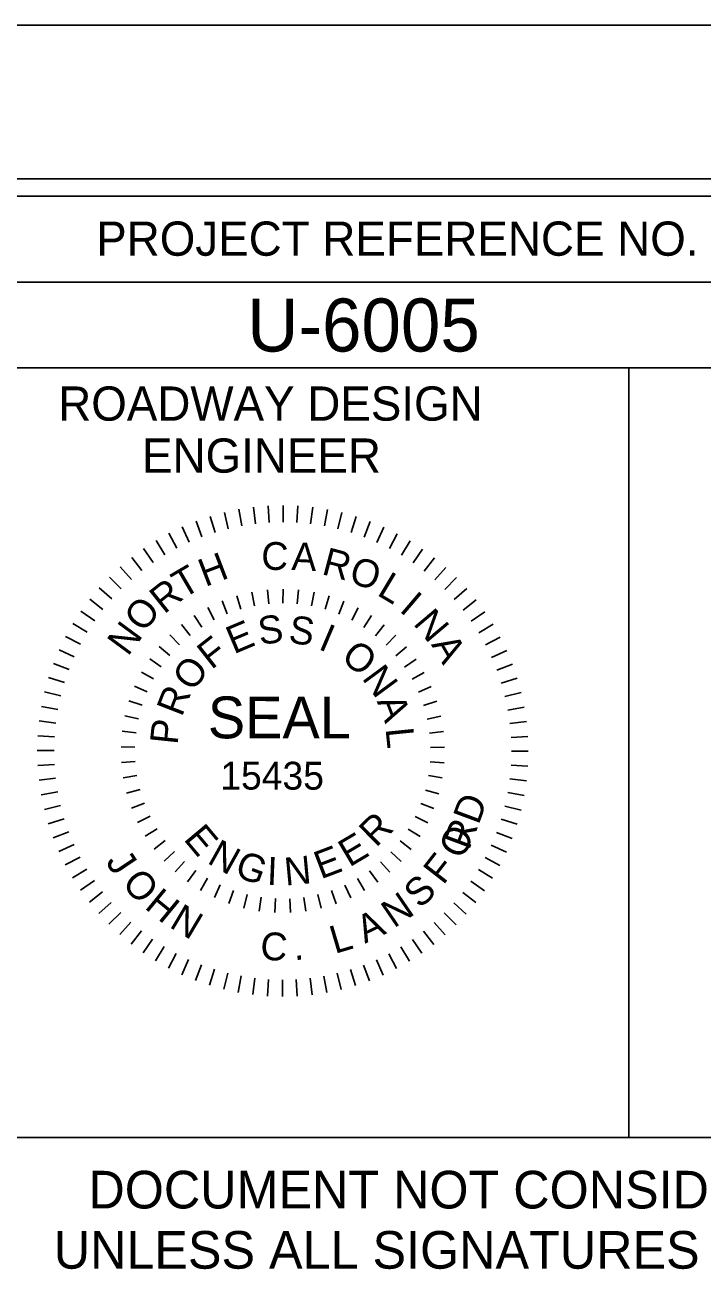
# Model space of a CAD drawing. Extents: x 1624665 to 1626605, y 896887 to 897987.
# Drawn here: x 1626144.2 to 1626243.2, y 897803.5 to 897987.4 of the extents above; entities that cross this region are included whole.
import ezdxf

# ---------------------------------------------------------------- set-up
doc = ezdxf.new("R2010")
doc.units = 0
for name, color, linetype in [('Old_Level_21', 7, 'Continuous'), ('Sheet Cutting Line CELL', 7, 'Continuous'), ('Sheet Data Field CELL', 7, 'Continuous'), ('Sheet Plot Border Inside CELL', 7, 'Continuous'), ('Sheet Plot Border Outside CELL', 7, 'Continuous'), ('Sheet Profile CELL', 7, 'Continuous'), ('Sheet Profile Grid Major CELL', 7, 'Continuous'), ('Sheet Sticker Exception Certification CELL', 7, 'Continuous')]:
    doc.layers.add(name, color=color, linetype=linetype)

msp = doc.modelspace()

# ---------------------------------------------------------------- linework, layer by layer
at = {"layer": 'Old_Level_21'}
for p, q in [((1626173.3, 897916.24), (1626173.87, 897913.87)), ((1626175.41, 897916.7), (1626175.85, 897914.29)), ((1626177.56, 897917.02), (1626177.85, 897914.59)), ((1626179.72, 897917.21), (1626179.86, 897914.77)), ((1626181.88, 897917.27), (1626181.88, 897914.83)), ((1626184.05, 897917.2), (1626183.9, 897914.76)), ((1626186.21, 897917), (1626185.91, 897914.58)), ((1626188.35, 897916.68), (1626187.91, 897914.27)), ((1626190.47, 897916.22), (1626189.88, 897913.85)), ((1626167.15, 897914.13), (1626168.15, 897911.9)), ((1626169.16, 897914.96), (1626170.02, 897912.67)), ((1626171.2, 897915.67), (1626171.93, 897913.33)), ((1626192.56, 897915.64), (1626191.83, 897913.3)), ((1626194.6, 897914.93), (1626193.73, 897912.64)), ((1626196.6, 897914.09), (1626195.6, 897911.86)), ((1626165.2, 897913.19), (1626166.34, 897911.02)), ((1626198.55, 897913.14), (1626197.41, 897910.98)), ((1626161.49, 897910.95), (1626162.88, 897908.94)), ((1626163.31, 897912.12), (1626164.58, 897910.03)), ((1626200.44, 897912.07), (1626199.17, 897909.98)), ((1626202.26, 897910.89), (1626200.87, 897908.88)), ((1626159.75, 897909.67), (1626161.25, 897907.74)), ((1626204, 897909.61), (1626202.49, 897907.68)), ((1626156.5, 897906.8), (1626158.22, 897905.07)), ((1626158.08, 897908.28), (1626159.7, 897906.45)), ((1626205.67, 897908.22), (1626204.04, 897906.39)), ((1626207.24, 897906.73), (1626205.51, 897905)), ((1626155.01, 897905.22), (1626156.84, 897903.6)), ((1626179.58, 897904.93), (1626179.78, 897902.91)), ((1626181.87, 897905.04), (1626181.86, 897903)), ((1626181.86, 897903), (1626181.87, 897905.04)), ((1626184.15, 897904.93), (1626183.95, 897902.9)), ((1626208.72, 897905.15), (1626206.89, 897903.53)), ((1626153.62, 897903.56), (1626155.54, 897902.05)), ((1626172.95, 897903.31), (1626173.71, 897901.42)), ((1626175.1, 897904.06), (1626175.68, 897902.11)), ((1626177.32, 897904.61), (1626177.71, 897902.61)), ((1626186.41, 897904.59), (1626186.02, 897902.59)), ((1626188.63, 897904.05), (1626188.04, 897902.09)), ((1626190.78, 897903.28), (1626190.01, 897901.4)), ((1626210.11, 897903.48), (1626208.18, 897901.98)), ((1626152.33, 897901.82), (1626154.34, 897900.42)), ((1626170.87, 897902.35), (1626171.81, 897900.54)), ((1626192.85, 897902.32), (1626191.91, 897900.51)), ((1626211.39, 897901.73), (1626209.38, 897900.35)), ((1626151.15, 897900), (1626153.24, 897898.73)), ((1626167.05, 897899.85), (1626168.32, 897898.26)), ((1626168.9, 897901.19), (1626170.01, 897899.48)), ((1626194.82, 897901.16), (1626193.7, 897899.45)), ((1626196.67, 897899.81), (1626195.39, 897898.22)), ((1626212.57, 897899.91), (1626210.47, 897898.65)), ((1626150.08, 897898.11), (1626152.25, 897896.97)), ((1626165.34, 897898.34), (1626166.76, 897896.88)), ((1626198.38, 897898.29), (1626196.95, 897896.83)), ((1626213.63, 897898.02), (1626211.46, 897896.89)), ((1626149.14, 897896.16), (1626151.36, 897895.16)), ((1626163.78, 897896.67), (1626165.33, 897895.35)), ((1626199.93, 897896.62), (1626198.37, 897895.31)), ((1626214.57, 897896.07), (1626212.34, 897895.07)), ((1626148.3, 897894.16), (1626150.59, 897893.29)), ((1626162.39, 897894.85), (1626164.06, 897893.69)), ((1626201.32, 897894.8), (1626199.64, 897893.64)), ((1626215.4, 897894.07), (1626213.11, 897893.2)), ((1626147.59, 897892.12), (1626149.93, 897891.39)), ((1626161.18, 897892.92), (1626162.96, 897891.92)), ((1626202.52, 897892.86), (1626200.74, 897891.87)), ((1626216.11, 897892.02), (1626213.77, 897891.3)), ((1626160.16, 897890.87), (1626162.03, 897890.05)), ((1626203.53, 897890.81), (1626201.66, 897889.99)), ((1626147, 897890.03), (1626149.38, 897889.44)), ((1626159.35, 897888.73), (1626161.29, 897888.1)), ((1626204.33, 897888.67), (1626202.39, 897888.04)), ((1626216.69, 897889.93), (1626214.31, 897889.35)), ((1626146.55, 897887.91), (1626148.95, 897887.47)), ((1626158.75, 897886.53), (1626160.74, 897886.09)), ((1626217.14, 897887.81), (1626214.73, 897887.37)), ((1626146.22, 897885.77), (1626148.65, 897885.47)), ((1626204.93, 897886.46), (1626202.94, 897886.03)), ((1626217.46, 897885.67), (1626215.03, 897885.38)), ((1626146.02, 897883.61), (1626148.46, 897883.46)), ((1626158.36, 897884.27), (1626160.38, 897884.03)), ((1626205.31, 897884.21), (1626203.29, 897883.97)), ((1626217.65, 897883.51), (1626215.21, 897883.37)), ((1626145.95, 897881.44), (1626148.4, 897881.44)), ((1626158.19, 897882), (1626160.23, 897881.94)), ((1626205.48, 897881.93), (1626203.44, 897881.88)), ((1626217.71, 897881.34), (1626215.27, 897881.35)), ((1626146.01, 897879.27), (1626148.46, 897879.42)), ((1626158.24, 897879.71), (1626160.27, 897879.86)), ((1626205.42, 897879.65), (1626203.39, 897879.8)), ((1626217.65, 897879.17), (1626215.21, 897879.32)), ((1626146.21, 897877.12), (1626148.63, 897877.41)), ((1626158.52, 897877.44), (1626160.52, 897877.78)), ((1626203.14, 897877.79), (1626205.15, 897877.45)), ((1626217.45, 897877.02), (1626215.02, 897877.31)), ((1626159, 897875.21), (1626160.97, 897875.74)), ((1626204.64, 897875.14), (1626202.68, 897875.68)), ((1626146.53, 897874.97), (1626148.93, 897875.41)), ((1626159.71, 897873.03), (1626161.62, 897873.75)), ((1626203.93, 897872.97), (1626202.03, 897873.7)), ((1626217.12, 897874.87), (1626214.71, 897875.32)), ((1626146.98, 897872.86), (1626149.36, 897873.43)), ((1626160.62, 897870.94), (1626162.45, 897871.84)), ((1626203.02, 897870.88), (1626201.19, 897871.79)), ((1626216.66, 897872.76), (1626214.29, 897873.34)), ((1626147.56, 897870.76), (1626149.9, 897871.49)), ((1626161.72, 897868.94), (1626163.46, 897870.01)), ((1626201.91, 897868.89), (1626200.17, 897869.96)), ((1626216.08, 897870.67), (1626213.74, 897871.4)), ((1626148.26, 897868.72), (1626150.55, 897869.58)), ((1626163.02, 897867.06), (1626164.64, 897868.29)), ((1626200.61, 897867), (1626198.99, 897868.25)), ((1626215.37, 897868.62), (1626213.08, 897869.49)), ((1626149.09, 897866.71), (1626151.32, 897867.71)), ((1626164.49, 897865.31), (1626165.99, 897866.69)), ((1626199.13, 897865.26), (1626197.64, 897866.65)), ((1626214.53, 897866.62), (1626212.3, 897867.63)), ((1626150.04, 897864.76), (1626152.21, 897865.89)), ((1626166.12, 897863.71), (1626167.48, 897865.24)), ((1626197.49, 897863.67), (1626196.14, 897865.2)), ((1626213.58, 897864.67), (1626211.42, 897865.81)), ((1626151.1, 897862.87), (1626153.19, 897864.13)), ((1626167.91, 897862.28), (1626169.11, 897863.93)), ((1626169.81, 897861.02), (1626170.85, 897862.78)), ((1626193.8, 897860.99), (1626192.76, 897862.75)), ((1626195.71, 897862.24), (1626194.51, 897863.89)), ((1626212.51, 897862.78), (1626210.42, 897864.06)), ((1626152.27, 897861.05), (1626154.29, 897862.44)), ((1626153.56, 897859.3), (1626155.48, 897860.81)), ((1626171.84, 897859.96), (1626172.7, 897861.81)), ((1626173.95, 897859.09), (1626174.63, 897861.02)), ((1626189.65, 897859.07), (1626188.97, 897861)), ((1626191.77, 897859.93), (1626190.91, 897861.78)), ((1626210.05, 897859.23), (1626208.13, 897860.73)), ((1626211.33, 897860.97), (1626209.33, 897862.36)), ((1626154.94, 897857.63), (1626156.77, 897859.25)), ((1626176.62, 897860.42), (1626176.13, 897858.44)), ((1626178.38, 897858), (1626178.68, 897860.01)), ((1626180.66, 897857.77), (1626180.76, 897859.81)), ((1626182.94, 897857.77), (1626182.85, 897859.8)), ((1626185.22, 897857.99), (1626184.93, 897860)), ((1626187.46, 897858.42), (1626186.97, 897860.4)), ((1626208.66, 897857.56), (1626206.83, 897859.18)), ((1626156.43, 897856.06), (1626158.16, 897857.78)), ((1626207.17, 897855.99), (1626205.44, 897857.72)), ((1626158, 897854.57), (1626159.63, 897856.39)), ((1626205.59, 897854.5), (1626203.97, 897856.33)), ((1626159.67, 897853.18), (1626161.17, 897855.1)), ((1626161.41, 897851.89), (1626162.8, 897853.9)), ((1626202.18, 897851.83), (1626200.79, 897853.85)), ((1626203.92, 897853.11), (1626202.42, 897855.04)), ((1626163.23, 897850.71), (1626164.5, 897852.8)), ((1626165.11, 897849.64), (1626166.25, 897851.81)), ((1626198.46, 897849.6), (1626197.33, 897851.76)), ((1626200.36, 897850.66), (1626199.09, 897852.75)), ((1626167.06, 897848.69), (1626168.07, 897850.92)), ((1626169.06, 897847.86), (1626169.94, 897850.15)), ((1626194.51, 897847.82), (1626193.64, 897850.11)), ((1626196.51, 897848.65), (1626195.51, 897850.88)), ((1626171.11, 897847.15), (1626171.84, 897849.49)), ((1626173.2, 897846.56), (1626173.78, 897848.94)), ((1626175.32, 897846.11), (1626175.76, 897848.51)), ((1626177.46, 897845.78), (1626177.75, 897848.2)), ((1626179.62, 897845.58), (1626179.77, 897848.02)), ((1626181.78, 897845.51), (1626181.79, 897847.96)), ((1626183.95, 897845.57), (1626183.81, 897848.01)), ((1626186.11, 897845.77), (1626185.82, 897848.19)), ((1626188.25, 897846.09), (1626187.82, 897848.49)), ((1626190.37, 897846.54), (1626189.79, 897848.91)), ((1626192.46, 897847.12), (1626191.74, 897849.46))]:
    msp.add_line(p, q, dxfattribs=at)
at = {"layer": 'Sheet Cutting Line CELL'}
msp.add_line((1626349.4, 897987.44), (1624665.4, 897987.44), dxfattribs=at)
at = {"layer": 'Sheet Plot Border Inside CELL'}
msp.add_lwpolyline([(1624678.4, 896909.89), (1626344.9, 896909.89), (1626344.9, 897964.99), (1624678.4, 897964.99)], close=True, dxfattribs=at)
at = {"layer": 'Sheet Plot Border Outside CELL'}
msp.add_lwpolyline([(1624665.4, 896887.44), (1626349.4, 896887.44), (1626349.4, 897987.44), (1624665.4, 897987.44)], close=True, dxfattribs=at)
at = {"layer": 'Sheet Profile CELL'}
for p, q in [((1626132.35, 897949.89), (1626332.4, 897949.89)), ((1626232.4, 897937.39), (1626232.4, 897824.94))]:
    msp.add_line(p, q, dxfattribs=at)
for points in [[(1626332.4, 897962.44), (1624832.4, 897962.44), (1624832.4, 896912.44), (1626332.4, 896912.44)], [(1626132.35, 897962.44), (1626332.4, 897962.44), (1626332.4, 897937.39), (1626132.35, 897937.39)], [(1626132.35, 897937.39), (1626232.4, 897937.39), (1626232.4, 897824.89), (1626132.35, 897824.89)], [(1626232.4, 897937.39), (1626332.4, 897937.39), (1626332.4, 897824.89), (1626232.4, 897824.89)]]:
    msp.add_lwpolyline(points, close=True, dxfattribs=at)
at = {"layer": 'Sheet Profile Grid Major CELL'}
msp.add_lwpolyline([(1625582.4, 897462.44), (1625632.4, 897462.44), (1625632.4, 897962.44), (1625682.4, 897962.44), (1625682.4, 897462.44), (1625732.4, 897462.44), (1625732.4, 897962.44), (1625782.4, 897962.44), (1625782.4, 897462.44), (1625832.4, 897462.44), (1625832.4, 897962.44), (1625882.4, 897962.44), (1625882.4, 897462.44), (1625932.4, 897462.44), (1625932.4, 897962.44), (1625982.4, 897962.44), (1625982.4, 897462.44), (1626032.4, 897462.44), (1626032.4, 897962.44), (1626082.4, 897962.44), (1626082.4, 897462.44), (1626132.4, 897462.44), (1626132.4, 897962.44), (1626158.7, 897962.44)], dxfattribs=at)
at = {"layer": 'Sheet Sticker Exception Certification CELL'}
msp.add_line((1626132.35, 897824.89), (1626332.39, 897824.89), dxfattribs=at)
msp.add_line((1626132.35, 897824.89), (1626332.39, 897824.89), dxfattribs=at)

# ---------------------------------------------------------------- texts
at = {"layer": 'Old_Level_21'}
for s, height, rotation, p in [('C', 4.07, 357.2771, (1626178.61, 897907.94)), ('A', 4.07, 357.2771, (1626183.06, 897907.85)), ('R', 4.07, 345.2678, (1626187.38, 897907.25)), ('T', 4.07, 30.4198, (1626167.22, 897903.56)), ('H', 4.07, 20.9878, (1626170.5, 897905.33)), ('O', 4.07, 342.211, (1626191.32, 897906.07)), ('L', 4.07, 329.0747, (1626195.46, 897904.25)), ('R', 4.07, 38.5807, (1626164.48, 897901.29)), ('O', 4.07, 51.6375, (1626161.52, 897898.55)), ('I', 4.07, 319.4993, (1626198.74, 897901.88)), ('S', 4.07, 7.5683, (1626178.49, 897896.88)), ('N', 4.07, 310.2048, (1626200.78, 897899.96)), ('N', 4.07, 53.5969, (1626159.18, 897895.11)), ('E', 4.07, 22.8645, (1626174.67, 897895.49)), ('S', 4.07, 352.272, (1626182.56, 897897.22)), ('I', 4.07, 336.9758, (1626186.89, 897896.33)), ('F', 4.07, 38.1608, (1626171.4, 897893.19)), ('A', 4.07, 300.4373, (1626203.47, 897896.94)), ('O', 4.07, 321.6795, (1626190.17, 897894.74)), ('O', 4.07, 53.457, (1626168.69, 897889.91)), ('N', 4.07, 306.3833, (1626193.31, 897892.01)), ('R', 4.07, 68.7533, (1626167.07, 897886.25)), ('SEAL', 6.114, 359.9202, (1626170.88, 897883.24)), ('A', 4.07, 291.0871, (1626195.54, 897888.67)), ('P', 4.07, 84.0495, (1626166.45, 897882.22)), ('L', 4.07, 275.7908, (1626196.85, 897884.64)), ('15435', 4.073, 359.9202, (1626172.7, 897875.75)), (' RD', 4.073, 69.5926, (1626208.54, 897865.38)), ('R', 4.07, 44.4851, (1626195.46, 897867.18)), ('E', 4.07, 309.9903, (1626167.22, 897868.48)), ('O ', 4.073, 60.9198, (1626207.95, 897865.37)), ('N', 4.07, 330.8453, (1626170.63, 897865.08)), ('E', 4.07, 30.714, (1626191.57, 897864.34)), ('J', 4.07, 303.8552, (1626155.85, 897865.16)), ('G', 4.07, 339.6116, (1626174.62, 897863.16)), ('E', 4.07, 20.7281, (1626187.39, 897862.61)), ('F', 4.07, 52.1272, (1626205.29, 897861.69)), ('I', 4.07, 357.7064, (1626179.47, 897861.85)), ('N', 4.07, 5.336, (1626182.23, 897861.71)), ('O', 4.07, 311.927, (1626158.17, 897861.92)), ('S', 4.07, 43.2446, (1626201.9, 897858.24)), ('H', 4.07, 320.5697, (1626161.49, 897858.48)), ('N', 4.07, 34.362, (1626198.08, 897855.42)), ('N', 4.07, 329.2423, (1626165.1, 897855.72)), ('A', 4.07, 25.5393, (1626193.84, 897853.2)), ('L', 4.07, 16.5368, (1626189.44, 897851.72)), ('C', 4.07, 356.0101, (1626178.45, 897850.94)), ('.', 4.07, 3.7525, (1626183.51, 897850.82))]:
    msp.add_text(s, height=height, rotation=rotation, dxfattribs=at).set_placement(p)
at = {"layer": 'Sheet Data Field CELL'}
msp.add_text('U-6005', height=7.75, dxfattribs=at).set_placement((1626176.64, 897939.75))
at = {"layer": 'Sheet Profile CELL'}
for s, height, p in [('PROJECT REFERENCE NO.', 5.0001, (1626154.56, 897953.75)), ('ROADWAY DESIGN', 5.0001, (1626149.01, 897929.65)), ('ENGINEER', 5, (1626161.26, 897922.05))]:
    msp.add_text(s, height=height, dxfattribs=at).set_placement(p)
at = {"layer": 'Sheet Sticker Exception Certification CELL'}
for s, p in [('DOCUMENT NOT CONSIDERED FINAL', (1626153.42, 897814.54)), ('DOCUMENT NOT CONSIDERED FINAL', (1626153.42, 897814.54)), ('UNLESS ALL SIGNATURES COMPLETED', (1626148.35, 897805.74)), ('UNLESS ALL SIGNATURES COMPLETED', (1626148.35, 897805.74))]:
    msp.add_text(s, height=5.5, dxfattribs=at).set_placement(p)

doc.saveas('drawing.dxf')
